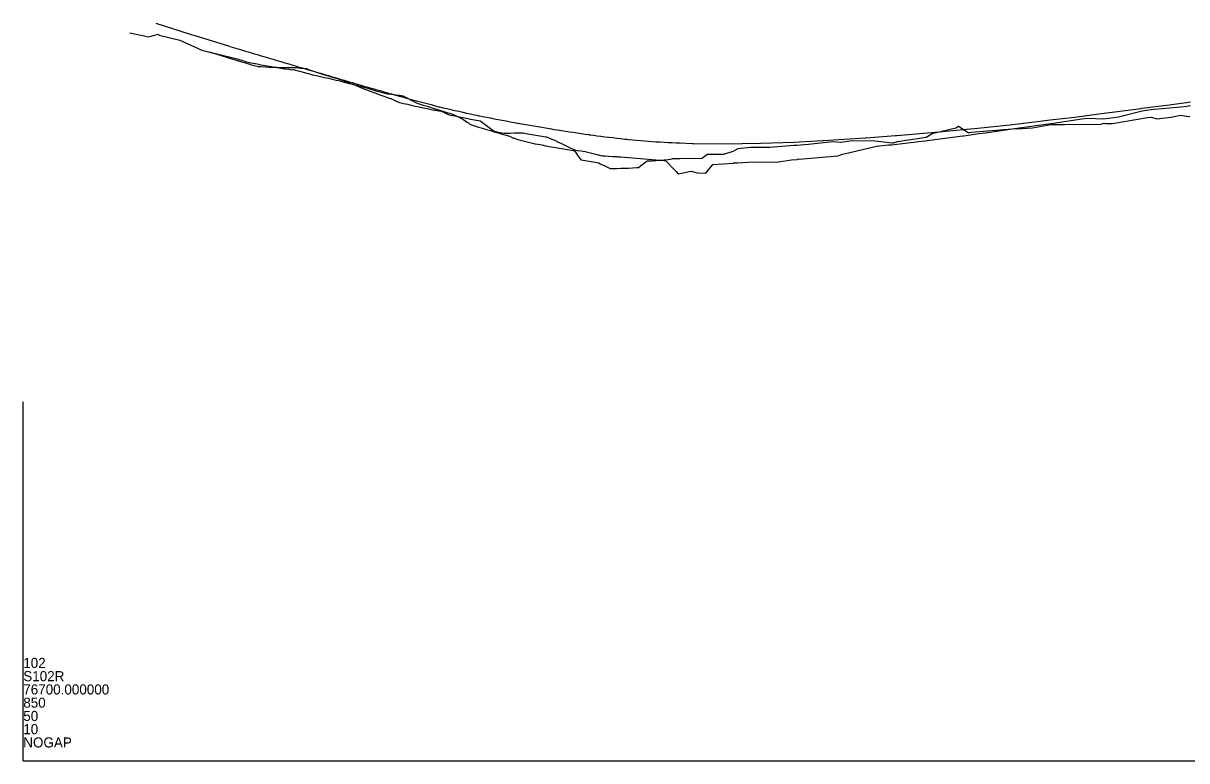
# Model space of a CAD drawing. Extents: x 1558113 to 1562835, y 1129435 to 1135883.
# Drawn here: x 1558196 to 1559007, y 1133444 to 1133957 of the extents above; entities that cross this region are included whole.
import ezdxf

# ---------------------------------------------------------------- set-up
doc = ezdxf.new("R2010")
doc.units = 0
for name, color, linetype in [('BR_EXIST_GROUND_LT', 7, 'Continuous'), ('BR_EXIST_GROUND_RT', 7, 'Continuous'), ('RD_DDB_Profile_EX', 7, 'Continuous'), ('RD_GPK_Profile_Cell', 7, 'Continuous')]:
    doc.layers.add(name, color=color, linetype=linetype)

msp = doc.modelspace()

# ---------------------------------------------------------------- linework, layer by layer
at = {"layer": 'BR_EXIST_GROUND_LT'}
msp.add_lwpolyline([(1558326.01, 1133937.47), (1558326.65, 1133937.25), (1558326.99, 1133937.1), (1558327.33, 1133937.03), (1558348.29, 1133930.58), (1558351.04, 1133929.75), (1558353.8, 1133928.91), (1558355.11, 1133928.51), (1558356.55, 1133928.15), (1558357.13, 1133928), (1558359.3, 1133927.47), (1558359.78, 1133927.36), (1558362.05, 1133927.2), (1558364.8, 1133927.04), (1558367.55, 1133926.9), (1558370.3, 1133926.78), (1558373.05, 1133926.69), (1558375.81, 1133926.63), (1558378.56, 1133926.58), (1558381.31, 1133926.57), (1558384.06, 1133926.58), (1558385.93, 1133926.6), (1558386.81, 1133926.49), (1558389.56, 1133926.17), (1558390.83, 1133926.06), (1558392.31, 1133925.9), (1558393.52, 1133925.78), (1558395.06, 1133925.22), (1558397.82, 1133924.27), (1558400.57, 1133923.34), (1558403.32, 1133922.44), (1558406.07, 1133921.56), (1558408.82, 1133920.71), (1558411.57, 1133919.88), (1558414.32, 1133919.08), (1558417.07, 1133918.3), (1558418.23, 1133917.99), (1558419.83, 1133917.31), (1558422.58, 1133916.16), (1558423.56, 1133915.76), (1558424.44, 1133915.53), (1558425.33, 1133915.15), (1558428.08, 1133914), (1558430.83, 1133912.87), (1558433.58, 1133911.77), (1558436.33, 1133910.69), (1558439.09, 1133909.64), (1558441.84, 1133908.61), (1558444.59, 1133907.6), (1558447.34, 1133906.62), (1558450.12, 1133905.65), (1558452.1, 1133905.01), (1558452.47, 1133904.89), (1558452.84, 1133904.72), (1558455.59, 1133903.44), (1558458.34, 1133902.24), (1558461.1, 1133901.57), (1558463.85, 1133900.92), (1558466.6, 1133900.28), (1558469.35, 1133899.67), (1558472.1, 1133899.08), (1558474.85, 1133898.51), (1558477.6, 1133897.95), (1558480.35, 1133897.42), (1558482.76, 1133896.97), (1558483.11, 1133896.9), (1558485.86, 1133896.41), (1558487.45, 1133896.13), (1558488.61, 1133895.6), (1558491.36, 1133894.38), (1558492.97, 1133893.67), (1558494.11, 1133893.43), (1558496.86, 1133892.85), (1558499.61, 1133892.29), (1558502.36, 1133891.75), (1558505.12, 1133891.22), (1558507.87, 1133890.7), (1558510.62, 1133890.2), (1558513.37, 1133889.72), (1558514.49, 1133889.52), (1558516.12, 1133888.26), (1558518.87, 1133886.15), (1558521.62, 1133884.03), (1558524.37, 1133882.19), (1558525.52, 1133881.9), (1558527.13, 1133881.63), (1558529.88, 1133881.16), (1558531.26, 1133880.93), (1558532.63, 1133880.94), (1558535.38, 1133880.95), (1558538.13, 1133880.97), (1558540.88, 1133880.98), (1558543.63, 1133880.99), (1558544.45, 1133880.99), (1558546.38, 1133880.68), (1558549.14, 1133880.22), (1558551.89, 1133879.77), (1558554.64, 1133879.31), (1558557.39, 1133878.85), (1558560.14, 1133878.38), (1558560.68, 1133878.29), (1558562.89, 1133877.32), (1558565.64, 1133876.11), (1558567.81, 1133875.16), (1558568.39, 1133874.88), (1558571.15, 1133873.57), (1558573.9, 1133872.25), (1558576.65, 1133870.93), (1558579.4, 1133869.61), (1558580.36, 1133869.15), (1558582.15, 1133868.88), (1558584.9, 1133868.47), (1558587.65, 1133868.04), (1558588.26, 1133867.95), (1558590.4, 1133867.39), (1558593.16, 1133866.67), (1558595.91, 1133865.94), (1558598.66, 1133865.21), (1558599.78, 1133865.07), (1558601.41, 1133864.99), (1558604.16, 1133864.84), (1558606.91, 1133864.67), (1558609.66, 1133864.5), (1558610.47, 1133864.45), (1558612.41, 1133864.32), (1558615.17, 1133864.13), (1558617.92, 1133863.93), (1558620.67, 1133863.72), (1558623.42, 1133863.51), (1558626.17, 1133863.28), (1558628.92, 1133863.04), (1558631.67, 1133862.79), (1558634.42, 1133862.54), (1558637.18, 1133862.27), (1558639.93, 1133862), (1558640.37, 1133861.96), (1558642.68, 1133861.88), (1558643.53, 1133861.84), (1558645.43, 1133859.88), (1558648.18, 1133857), (1558650.93, 1133854.1), (1558652.48, 1133852.45), (1558653.68, 1133852.71), (1558661.51, 1133854.36), (1558665.59, 1133853.13), (1558671.76, 1133852.96), (1558676.56, 1133859.03), (1558690.89, 1133859.93), (1558691.63, 1133860.41), (1558692.16, 1133860.25), (1558693.77, 1133860.16), (1558704.65, 1133860.79), (1558720.78, 1133860.73), (1558722.4, 1133860.78), (1558731.43, 1133862.25), (1558735.3, 1133862.44), (1558735.86, 1133862.78), (1558736.22, 1133862.86), (1558736.65, 1133862.73), (1558763.58, 1133865.17), (1558766.82, 1133866.15), (1558770.99, 1133867.13), (1558790.46, 1133871.69), (1558798.93, 1133872.64), (1558800.94, 1133872.83), (1558820, 1133875.02), (1558824.28, 1133875.42), (1558850.72, 1133878.97), (1558851.4, 1133879.06), (1558862.01, 1133880.58), (1558866.36, 1133881.14), (1558889.93, 1133884.44), (1558895.28, 1133885.2), (1558903, 1133886.32), (1558912.25, 1133887.64), (1558933.48, 1133890.74), (1558937.15, 1133891.23), (1558948.65, 1133890.86), (1558959.01, 1133892.24), (1558975.57, 1133896.4), (1558981.59, 1133897.21), (1559002.54, 1133899.15), (1559006.44, 1133899.67), (1559009.18, 1133900.04)], dxfattribs=at)
at = {"layer": 'BR_EXIST_GROUND_RT'}
msp.add_lwpolyline([(1558270.54, 1133950.8), (1558283.72, 1133947.99), (1558290.33, 1133949.78), (1558291, 1133949.14), (1558305.38, 1133945.51), (1558320.6, 1133938.65), (1558344.32, 1133932.9), (1558348.29, 1133931.64), (1558350.5, 1133930.92), (1558351.04, 1133930.75), (1558353.8, 1133930.09), (1558354.56, 1133929.92), (1558356.55, 1133929.53), (1558359.3, 1133929.02), (1558362.05, 1133928.52), (1558364.8, 1133928.02), (1558367.55, 1133927.54), (1558370.3, 1133927.08), (1558373.05, 1133926.62), (1558375.81, 1133926.18), (1558378.56, 1133925.75), (1558381.31, 1133925.34), (1558383.23, 1133925.05), (1558384.34, 1133925.17), (1558386.92, 1133924.53), (1558389.56, 1133923.8), (1558392.31, 1133923.06), (1558393.68, 1133922.69), (1558395.06, 1133922.32), (1558396.25, 1133921.92), (1558397.82, 1133921.57), (1558400.57, 1133920.94), (1558403.32, 1133920.32), (1558406.07, 1133919.7), (1558408.82, 1133919.08), (1558411.57, 1133918.47), (1558414.32, 1133917.86), (1558415.77, 1133917.55), (1558417.07, 1133917.19), (1558419.83, 1133916.44), (1558422.58, 1133915.69), (1558425.33, 1133914.95), (1558428.08, 1133914.2), (1558430.83, 1133913.47), (1558431.63, 1133913.25), (1558433.58, 1133912.79), (1558435.44, 1133912.36), (1558436.33, 1133912.07), (1558437.63, 1133911.65), (1558439.09, 1133911.23), (1558441.84, 1133910.43), (1558444.59, 1133909.64), (1558447.34, 1133908.85), (1558448.97, 1133908.39), (1558450.09, 1133908.25), (1558452.84, 1133907.9), (1558455.59, 1133907.55), (1558458.34, 1133907.21), (1558460.61, 1133906.92), (1558461.1, 1133906.67), (1558463.85, 1133905.23), (1558466.6, 1133903.8), (1558469.35, 1133902.36), (1558470.66, 1133901.67), (1558471.42, 1133901.46), (1558472.1, 1133901.25), (1558474.85, 1133900.39), (1558477.6, 1133899.53), (1558480.35, 1133898.67), (1558483.11, 1133897.82), (1558485.86, 1133896.98), (1558488.61, 1133896.14), (1558491.36, 1133895.3), (1558494.11, 1133894.47), (1558495.28, 1133894.11), (1558496.86, 1133893.31), (1558499.61, 1133891.93), (1558502.36, 1133890.55), (1558503.1, 1133890.18), (1558505.12, 1133888.81), (1558506.34, 1133887.99), (1558507.25, 1133887.06), (1558507.87, 1133886.86), (1558510.62, 1133885.98), (1558513.37, 1133885.12), (1558516.12, 1133884.28), (1558518.87, 1133883.44), (1558521.62, 1133882.62), (1558524.37, 1133881.81), (1558527.13, 1133881.02), (1558529.88, 1133880.24), (1558532.63, 1133879.47), (1558534.97, 1133878.83), (1558535.38, 1133878.61), (1558537.71, 1133877.37), (1558538.13, 1133877.25), (1558540.88, 1133876.49), (1558543.63, 1133875.76), (1558546.38, 1133875.03), (1558549.14, 1133874.33), (1558551.89, 1133873.64), (1558552.51, 1133873.48), (1558554.64, 1133873.18), (1558557.39, 1133872.64), (1558560.14, 1133872.11), (1558562.89, 1133871.6), (1558565.64, 1133871.11), (1558568.39, 1133870.62), (1558571.15, 1133870.16), (1558573.9, 1133869.71), (1558576.65, 1133869.27), (1558579.4, 1133868.86), (1558580.18, 1133868.74), (1558582.15, 1133865.81), (1558584.55, 1133862.28), (1558584.9, 1133862.21), (1558587.65, 1133861.74), (1558590.4, 1133861.29), (1558593.16, 1133860.86), (1558595.91, 1133860.47), (1558597.28, 1133860.28), (1558598.21, 1133859.54), (1558598.66, 1133859.32), (1558601.41, 1133858.03), (1558604.16, 1133856.76), (1558605.1, 1133856.34), (1558606.91, 1133856.33), (1558609.66, 1133856.34), (1558612.41, 1133856.39), (1558615.17, 1133856.47), (1558617.92, 1133856.58), (1558620.67, 1133856.73), (1558623.42, 1133856.9), (1558624.77, 1133857), (1558626.17, 1133858.04), (1558628.92, 1133860.1), (1558630.72, 1133861.47), (1558631.67, 1133861.51), (1558634.42, 1133861.64), (1558637.18, 1133861.8), (1558639.93, 1133861.98), (1558641.85, 1133862.12), (1558642.68, 1133862.23), (1558645.43, 1133862.61), (1558648.18, 1133863.02), (1558648.61, 1133863.09), (1558650.93, 1133863.1), (1558653.68, 1133863.12), (1558669.23, 1133863.32), (1558672.65, 1133866.2), (1558684.23, 1133866.29), (1558690.8, 1133868.23), (1558694.26, 1133870.07), (1558702.85, 1133871.03), (1558716.23, 1133871.05), (1558732.85, 1133872.59), (1558734.51, 1133872.5), (1558734.98, 1133872.55), (1558743.1, 1133873.08), (1558759.95, 1133875.12), (1558765.42, 1133874.54), (1558766.04, 1133874.62), (1558773.28, 1133875.74), (1558789.37, 1133875.48), (1558801.4, 1133874.19), (1558802.28, 1133874.16), (1558805.15, 1133875.02), (1558825.21, 1133878.01), (1558829.29, 1133880.5), (1558845.83, 1133884.63), (1558847.6, 1133885.75), (1558854.33, 1133881.32), (1558855.29, 1133881.34), (1558856.42, 1133881.49), (1558884.95, 1133883.89), (1558886.42, 1133884.06), (1558888.17, 1133883.78), (1558899.07, 1133884.63), (1558911.91, 1133886.87), (1558921.48, 1133886.88), (1558946.77, 1133886.99), (1558949.06, 1133887.69), (1558949.89, 1133887.55), (1558954.81, 1133887.5), (1558979.15, 1133891.79), (1558982.08, 1133892.08), (1558985.82, 1133890.92), (1558995.73, 1133892.01), (1559002.33, 1133893.34), (1559006.44, 1133892.72), (1559008.75, 1133892.38)], dxfattribs=at)
at = {"layer": 'RD_DDB_Profile_EX'}
msp.add_lwpolyline([(1558288.67, 1133957.37), (1558313.4, 1133949.66), (1558314.29, 1133949.36), (1558315.14, 1133949.08), (1558339.92, 1133941.38), (1558340.31, 1133941.26), (1558348.29, 1133938.87), (1558351.17, 1133938), (1558353.8, 1133937.21), (1558356.55, 1133936.37), (1558359.3, 1133935.54), (1558362.05, 1133934.71), (1558363.79, 1133934.19), (1558364.8, 1133933.89), (1558367.55, 1133933.08), (1558370.3, 1133932.26), (1558373.05, 1133931.45), (1558375.81, 1133930.64), (1558378.56, 1133929.82), (1558381.31, 1133929.01), (1558384.06, 1133928.19), (1558386.81, 1133927.38), (1558387.24, 1133927.25), (1558387.66, 1133927.14), (1558389.56, 1133926.58), (1558392.31, 1133925.77), (1558395.06, 1133924.96), (1558397.82, 1133924.15), (1558400.57, 1133923.34), (1558403.32, 1133922.52), (1558406.07, 1133921.71), (1558408.82, 1133920.89), (1558411.57, 1133920.08), (1558412.61, 1133919.77), (1558413.46, 1133919.53), (1558414.35, 1133919.27), (1558417.07, 1133918.48), (1558419.83, 1133917.68), (1558422.58, 1133916.88), (1558425.33, 1133916.08), (1558428.08, 1133915.27), (1558430.83, 1133914.47), (1558433.58, 1133913.66), (1558436.33, 1133912.85), (1558439.27, 1133911.98), (1558440.68, 1133911.6), (1558441.84, 1133911.27), (1558444.59, 1133910.5), (1558447.34, 1133909.72), (1558450.09, 1133908.94), (1558452.84, 1133908.16), (1558455.59, 1133907.38), (1558458.34, 1133906.59), (1558461.1, 1133905.81), (1558463.85, 1133905.03), (1558466.6, 1133904.31), (1558469.35, 1133903.59), (1558472.1, 1133902.87), (1558474.85, 1133902.15), (1558477.6, 1133901.42), (1558480.35, 1133900.7), (1558483.11, 1133899.97), (1558485.86, 1133899.24), (1558486.31, 1133899.12), (1558487.84, 1133898.72), (1558488.61, 1133898.54), (1558491.36, 1133897.94), (1558494.11, 1133897.32), (1558496.86, 1133896.71), (1558499.61, 1133896.1), (1558502.36, 1133895.48), (1558505.12, 1133894.86), (1558507.87, 1133894.24), (1558510.62, 1133893.62), (1558512.24, 1133893.26), (1558513.37, 1133893), (1558514.06, 1133892.84), (1558516.12, 1133892.46), (1558518.87, 1133891.94), (1558521.62, 1133891.43), (1558524.37, 1133890.91), (1558527.13, 1133890.39), (1558529.88, 1133889.87), (1558532.63, 1133889.35), (1558535.38, 1133888.83), (1558538.35, 1133888.27), (1558540.3, 1133887.88), (1558540.88, 1133887.78), (1558543.63, 1133887.31), (1558546.38, 1133886.84), (1558549.14, 1133886.38), (1558551.89, 1133885.9), (1558554.64, 1133885.43), (1558557.39, 1133884.96), (1558560.14, 1133884.49), (1558562.89, 1133884.01), (1558564.24, 1133883.78), (1558565.93, 1133883.46), (1558568.39, 1133883.1), (1558571.15, 1133882.69), (1558573.9, 1133882.28), (1558576.65, 1133881.87), (1558579.4, 1133881.45), (1558582.15, 1133881.04), (1558584.9, 1133880.63), (1558587.65, 1133880.21), (1558589.87, 1133879.88), (1558590.4, 1133879.79), (1558591.56, 1133879.61), (1558593.16, 1133879.41), (1558595.91, 1133879.08), (1558598.66, 1133878.74), (1558601.41, 1133878.4), (1558604.16, 1133878.07), (1558606.91, 1133877.73), (1558609.66, 1133877.39), (1558612.41, 1133877.05), (1558613.34, 1133876.93), (1558615.17, 1133876.72), (1558616.62, 1133876.61), (1558617.92, 1133876.5), (1558620.67, 1133876.27), (1558623.42, 1133876.04), (1558626.17, 1133875.81), (1558628.92, 1133875.58), (1558631.67, 1133875.34), (1558634.42, 1133875.11), (1558637.18, 1133874.87), (1558638.41, 1133874.76), (1558639.96, 1133874.69), (1558642.68, 1133874.56), (1558645.43, 1133874.43), (1558648.18, 1133874.29), (1558650.93, 1133874.16), (1558653.68, 1133874.02), (1558662.16, 1133873.61), (1558663.04, 1133873.59), (1558686.12, 1133873.45), (1558696.96, 1133873.7), (1558709.66, 1133873.97), (1558732.96, 1133874.46), (1558752.85, 1133875.7), (1558753.39, 1133875.75), (1558782.73, 1133877.58), (1558783.38, 1133877.63), (1558803.74, 1133879.24), (1558804.08, 1133879.27), (1558804.58, 1133879.32), (1558834.27, 1133881.66), (1558853.24, 1133883.58), (1558858.88, 1133884.15), (1558883.33, 1133886.61), (1558898.72, 1133888.47), (1558911.47, 1133890.01), (1558928.71, 1133892.08), (1558945.25, 1133894.23), (1558974.74, 1133898.07), (1558975.24, 1133898.14), (1558994.47, 1133900.65), (1558995.92, 1133900.87), (1559006.44, 1133902.26), (1559009.18, 1133902.62)], dxfattribs=at)
at = {"layer": 'RD_GPK_Profile_Cell'}
for q in [(1558196.37, 1133693.84), (1562834.74, 1133443.84), (1558196.37, 1133443.84)]:
    msp.add_line((1558196.37, 1133443.84), q, dxfattribs=at)

# ---------------------------------------------------------------- texts
for s, p in [('102', (1558196.37, 1133508.45)), ('S102R', (1558196.37, 1133499.22)), ('76700.000000', (1558196.37, 1133489.99)), ('850', (1558196.37, 1133480.76)), ('50', (1558196.37, 1133471.53)), ('10', (1558196.37, 1133462.3)), ('NOGAP', (1558196.37, 1133453.07))]:
    msp.add_text(s, height=7, dxfattribs=at).set_placement(p)

doc.saveas('drawing.dxf')
